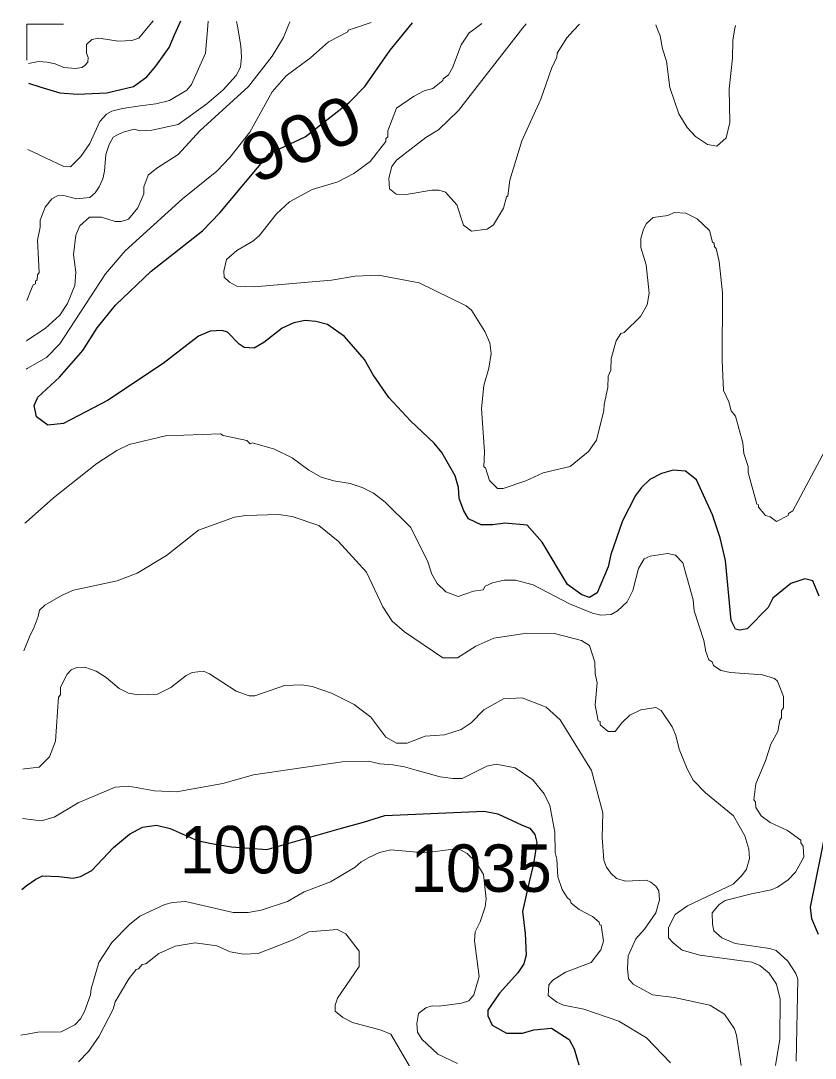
# Model space of a CAD drawing. Extents: x 598.3 to 623.2, y 6902.2 to 6930.1.
# Drawn here: x 598.538 to 599.877, y 6928.329 to 6930.078 of the extents above; entities that cross this region are included whole.
import ezdxf
from ezdxf.enums import TextEntityAlignment as Align

# ---------------------------------------------------------------- set-up
doc = ezdxf.new("R2010")
doc.units = 0
doc.header["$LTSCALE"] = 0.032
for name, color, linetype, lineweight in [('1', 7, 'Continuous', 25), ('2', 7, 'Continuous', 13), ('63', 7, 'Continuous', 13)]:
    doc.layers.add(name, color=color, linetype=linetype, lineweight=lineweight)
doc.layers.add('21', color=7, linetype='Continuous')
doc.layers.add('61', color=7, linetype='Continuous')

msp = doc.modelspace()

# ---------------------------------------------------------------- linework, layer by layer
at = {"layer": '1'}
for points in [[(598.5508, 6929.973), (598.5702, 6929.9669), (598.6037, 6929.9564), (598.6336, 6929.9544), (598.6832, 6929.9565), (598.7279, 6929.9674), (598.7506, 6929.9834), (598.7655, 6930.0018), (598.7878, 6930.0332), (598.7972, 6930.0545), (598.8074, 6930.0777)], [(599.8837, 6929.1081), (599.873, 6929.1342), (599.8597, 6929.1374), (599.8361, 6929.1298), (599.8058, 6929.1048), (599.7978, 6929.089), (599.7622, 6929.0534), (599.7495, 6929.051), (599.7426, 6929.0528), (599.7353, 6929.0671), (599.7257, 6929.1683), (599.7169, 6929.2068), (599.7042, 6929.2453), (599.6772, 6929.3043), (599.6586, 6929.3188), (599.6375, 6929.3205), (599.6181, 6929.3148), (599.5985, 6929.3049), (599.584, 6929.2911), (599.5741, 6929.2779), (599.552, 6929.235), (599.5324, 6929.1783), (599.528, 6929.1579), (599.5095, 6929.1141), (599.4966, 6929.1061), (599.4835, 6929.1102), (599.4593, 6929.1281), (599.4166, 6929.1995), (599.3916, 6929.228), (599.354, 6929.2314), (599.3335, 6929.2283), (599.3138, 6929.2283), (599.2928, 6929.2386), (599.2847, 6929.2522), (599.2768, 6929.2728), (599.2756, 6929.2913), (599.2699, 6929.311), (599.2478, 6929.3502), (599.2349, 6929.3661), (599.1947, 6929.4038), (599.1581, 6929.4429), (599.1318, 6929.4813), (599.1174, 6929.5072), (599.0835, 6929.5458), (599.0551, 6929.5663), (599.0353, 6929.5714), (599.0175, 6929.573), (598.998, 6929.569), (598.9787, 6929.5601), (598.9476, 6929.5357), (598.9313, 6929.5262), (598.9146, 6929.5275), (598.906, 6929.5332), (598.8862, 6929.5531), (598.8774, 6929.556), (598.857, 6929.5551), (598.8372, 6929.5467), (598.7781, 6929.5002), (598.6842, 6929.438), (598.6098, 6929.3992), (598.5835, 6929.3966), (598.5642, 6929.4104), (598.5602, 6929.4297), (598.5668, 6929.4436), (598.6032, 6929.4771), (598.6422, 6929.5222), (598.6667, 6929.5607), (598.6975, 6929.5987), (598.7574, 6929.6562), (598.844, 6929.7242), (598.8732, 6929.7541), (598.9571, 6929.8541), (599.0175, 6929.8825), (599.0919, 6929.9407), (599.118, 6929.9675), (599.1604, 6930.0286), (599.1983, 6930.0745)], [(598.5398, 6928.6138), (598.5469, 6928.6197), (598.5631, 6928.6313), (598.5745, 6928.6366), (598.6018, 6928.6356), (598.6261, 6928.6329), (598.6384, 6928.6355), (598.6578, 6928.6459), (598.6942, 6928.6848), (598.7211, 6928.7068), (598.743, 6928.7191), (598.7665, 6928.7222), (598.7895, 6928.7165), (598.8354, 6928.6966), (598.8591, 6928.6915), (598.893, 6928.6859), (598.9526, 6928.681), (599.0783, 6928.7169), (599.1158, 6928.7274), (599.1517, 6928.7388), (599.3189, 6928.7457), (599.3421, 6928.7415), (599.383, 6928.7224), (599.3959, 6928.7171), (599.4042, 6928.7065), (599.408, 6928.6928), (599.4024, 6928.6572), (599.3948, 6928.627), (599.3837, 6928.5767), (599.3883, 6928.5395), (599.3898, 6928.503), (599.386, 6928.4886), (599.376, 6928.4731), (599.3449, 6928.4391), (599.3254, 6928.4104), (599.3251, 6928.4009), (599.3326, 6928.3854), (599.3569, 6928.3718), (599.3836, 6928.3718), (599.4028, 6928.3774), (599.4324, 6928.3798), (599.4622, 6928.3607), (599.4706, 6928.3453), (599.4788, 6928.318)], [(599.8827, 6928.538), (599.8716, 6928.5641), (599.8691, 6928.584), (599.8966, 6928.7201)]]:
    msp.add_lwpolyline(points, dxfattribs=at)
at = {"layer": '2'}
for points in [[(598.5473, 6929.5383), (598.5482, 6929.5389), (598.5792, 6929.5596), (598.6038, 6929.582), (598.6165, 6929.6016), (598.629, 6929.6319), (598.6305, 6929.6546), (598.6266, 6929.6843), (598.6305, 6929.7169), (598.6374, 6929.7322), (598.6535, 6929.747), (598.6737, 6929.7471), (598.6967, 6929.7398), (598.7069, 6929.7398), (598.7193, 6929.7438), (598.7351, 6929.7627), (598.7454, 6929.7865), (598.7455, 6929.7984), (598.7524, 6929.818), (598.767, 6929.8299), (598.8031, 6929.8524), (598.8399, 6929.8925), (598.9217, 6929.967), (598.9616, 6930.0183), (598.9805, 6930.0496), (598.9884, 6930.0693), (598.9912, 6930.0762)], [(598.9016, 6930.0769), (598.903, 6930.0691), (598.9089, 6930.0361), (598.91, 6930.0168), (598.9085, 6930.0001), (598.9012, 6929.9859), (598.8791, 6929.9617), (598.8515, 6929.9382), (598.8032, 6929.9035), (598.7585, 6929.8935), (598.7388, 6929.8928), (598.7291, 6929.8951), (598.7102, 6929.8904), (598.7, 6929.8853), (598.6937, 6929.8817), (598.6868, 6929.8695), (598.6815, 6929.8529), (598.6792, 6929.8248), (598.6762, 6929.8118), (598.6701, 6929.7982), (598.6633, 6929.7883), (598.6542, 6929.78), (598.6319, 6929.7779), (598.6106, 6929.7836), (598.5995, 6929.783), (598.5904, 6929.7777), (598.5789, 6929.7637), (598.5707, 6929.7417), (598.5706, 6929.7301), (598.5658, 6929.708), (598.569, 6929.6535), (598.5658, 6929.6496), (598.5657, 6929.6414), (598.5626, 6929.6391), (598.5625, 6929.6348), (598.5589, 6929.6331), (598.5545, 6929.6225), (598.5478, 6929.6065)], [(598.5499, 6929.8611), (598.5797, 6929.8469), (598.6106, 6929.8322), (598.6214, 6929.8321), (598.6392, 6929.8493), (598.6542, 6929.8711), (598.6709, 6929.9083), (598.6823, 6929.9204), (598.6915, 6929.9259), (598.7096, 6929.9303), (598.739, 6929.9348), (598.7658, 6929.9379), (598.7884, 6929.9435), (598.8177, 6929.9609), (598.8259, 6929.9709), (598.8494, 6930.0235), (598.8524, 6930.0629), (598.8535, 6930.0773)], [(598.5511, 6930.0063), (598.5676, 6930.0092), (598.5825, 6930.0085), (598.5957, 6930.0054), (598.6104, 6929.9995), (598.6299, 6929.9978), (598.641, 6929.9994), (598.6455, 6930.0019), (598.6511, 6930.0085), (598.6514, 6930.0163), (598.6484, 6930.0237), (598.6484, 6930.0382), (598.6575, 6930.0465), (598.6697, 6930.049), (598.7028, 6930.0437), (598.7251, 6930.0448), (598.7367, 6930.0489), (598.7419, 6930.0551), (598.7612, 6930.0781)], [(599.1287, 6930.0751), (599.1005, 6930.0656), (599.0898, 6930.062), (599.0891, 6930.0593), (599.0568, 6930.0428), (599.0262, 6930.0156), (598.9853, 6929.9852), (598.9615, 6929.9581), (598.9242, 6929.8901), (598.8902, 6929.8474), (598.8683, 6929.8246), (598.8107, 6929.7782), (598.7139, 6929.6904), (598.6806, 6929.6513), (598.6038, 6929.5333), (598.581, 6929.5103), (598.5489, 6929.4922), (598.5469, 6929.4911)], [(599.3152, 6930.0736), (599.2996, 6930.0618), (599.2939, 6930.0575), (599.2804, 6930.0375), (599.2658, 6929.9986), (599.2588, 6929.987), (599.25, 6929.9803), (599.2495, 6929.9774), (599.2327, 6929.9641), (599.2177, 6929.9597), (599.1997, 6929.9507), (599.1711, 6929.9305), (599.1568, 6929.8926), (599.1566, 6929.8826), (599.1535, 6929.8796), (599.1534, 6929.8745), (599.1269, 6929.8411), (599.0992, 6929.8207), (599.0724, 6929.8068), (599.0289, 6929.7934), (598.9908, 6929.773), (598.9691, 6929.7529), (598.9399, 6929.7157), (598.929, 6929.7065), (598.902, 6929.6908), (598.8847, 6929.6755), (598.8799, 6929.6559), (598.8807, 6929.646), (598.8896, 6929.6374), (598.9023, 6929.6306), (598.9311, 6929.6296), (599.0619, 6929.6409), (599.1014, 6929.6475), (599.1411, 6929.649), (599.2092, 6929.6365), (599.2886, 6929.5975), (599.2977, 6929.5905), (599.3204, 6929.5542), (599.3283, 6929.5355), (599.3307, 6929.5174), (599.3268, 6929.4924), (599.3187, 6929.4635), (599.3146, 6929.4247), (599.3194, 6929.3515), (599.3186, 6929.3264), (599.3212, 6929.3247), (599.3282, 6929.303), (599.3414, 6929.2898), (599.3513, 6929.2898), (599.3893, 6929.3024), (599.4183, 6929.316), (599.4638, 6929.3268), (599.4949, 6929.3519), (599.5082, 6929.3713), (599.5209, 6929.4209), (599.5211, 6929.4312), (599.5274, 6929.4597), (599.5282, 6929.4788), (599.5323, 6929.4892), (599.5332, 6929.5089), (599.5418, 6929.5385), (599.5493, 6929.551), (599.5548, 6929.5529), (599.5825, 6929.5796), (599.5939, 6929.5992), (599.597, 6929.619), (599.5922, 6929.6669), (599.5834, 6929.6959), (599.5834, 6929.7111), (599.5875, 6929.727), (599.5928, 6929.7362), (599.6041, 6929.7463), (599.6284, 6929.7501), (599.6395, 6929.7551), (599.659, 6929.7536), (599.6782, 6929.7445), (599.6987, 6929.7247), (599.7041, 6929.705), (599.7069, 6929.7034), (599.7072, 6929.6973), (599.7103, 6929.6945), (599.7152, 6929.6721), (599.721, 6929.6194), (599.7201, 6929.5057), (599.7226, 6929.4546), (599.7313, 6929.4357), (599.7353, 6929.4205), (599.7427, 6929.4117), (599.7548, 6929.3664), (599.7567, 6929.3486), (599.7638, 6929.3269), (599.764, 6929.3167), (599.7784, 6929.2633), (599.7816, 6929.262), (599.7817, 6929.2584), (599.7933, 6929.2444), (599.8014, 6929.2417), (599.8116, 6929.234), (599.8313, 6929.244), (599.832, 6929.2476)], [(599.4797, 6930.0722), (599.4697, 6930.0615), (599.4584, 6930.0494), (599.4418, 6930.0233), (599.4415, 6930.0166), (599.4327, 6929.9978), (599.4148, 6929.946), (599.3825, 6929.8756), (599.3624, 6929.8094), (599.359, 6929.783), (599.3565, 6929.7815), (599.3516, 6929.7622), (599.335, 6929.7343), (599.3242, 6929.7269), (599.2974, 6929.7236), (599.2842, 6929.7333), (599.2729, 6929.7679), (599.2541, 6929.7892), (599.2425, 6929.7924), (599.2306, 6929.7924), (599.1875, 6929.7853), (599.1706, 6929.7859), (599.1597, 6929.7949), (599.1584, 6929.8129), (599.1633, 6929.8323), (599.1712, 6929.8433), (599.2206, 6929.8814), (599.2418, 6929.8942), (599.2756, 6929.9268), (599.3842, 6930.0661), (599.3896, 6930.073)], [(599.6083, 6930.0712), (599.6108, 6930.0651), (599.6158, 6930.0529), (599.6195, 6930.0306), (599.6262, 6930.0101), (599.6321, 6929.9654), (599.6471, 6929.9214), (599.6614, 6929.898), (599.675, 6929.8829), (599.6953, 6929.8693), (599.7111, 6929.8669), (599.7272, 6929.8805), (599.733, 6929.9066), (599.7322, 6929.9632), (599.7379, 6930.0148), (599.738, 6930.0447), (599.7412, 6930.0629), (599.7425, 6930.0701)], [(599.832, 6929.2476), (599.8395, 6929.2522), (599.9069, 6929.3782), (599.9183, 6929.4492), (599.9218, 6929.4577), (599.9257, 6929.4948), (599.9274, 6929.5591), (599.9233, 6929.6142), (599.9241, 6929.6345), (599.9325, 6929.6577), (599.9627, 6929.691), (599.9824, 6929.717), (599.9912, 6929.7349), (599.9969, 6929.7544), (599.9969, 6929.7754), (599.9872, 6929.833), (599.9937, 6929.913), (599.984, 6929.9468), (599.9734, 6930.0037), (599.976, 6930.0596), (599.9764, 6930.0681)], [(598.5448, 6929.2312), (598.5468, 6929.233), (598.5929, 6929.2739), (598.6662, 6929.332), (598.6997, 6929.354), (598.7207, 6929.3639), (598.7821, 6929.3787), (598.8747, 6929.3819), (598.8791, 6929.3789), (598.9187, 6929.3706), (598.9246, 6929.3651), (598.9287, 6929.3665), (598.9656, 6929.356), (598.9951, 6929.3414), (599.0237, 6929.3206), (599.0445, 6929.3086), (599.0654, 6929.3024), (599.0933, 6929.2979), (599.1136, 6929.2911), (599.1324, 6929.2816), (599.1523, 6929.2666), (599.1955, 6929.2241), (599.2243, 6929.166), (599.2306, 6929.1451), (599.2398, 6929.1298), (599.2542, 6929.1154), (599.2753, 6929.1077), (599.3011, 6929.1165), (599.3176, 6929.1191), (599.3209, 6929.1252), (599.3331, 6929.1309), (599.3529, 6929.1352), (599.3718, 6929.1352), (599.4018, 6929.1276), (599.463, 6929.0953), (599.5015, 6929.0793), (599.5155, 6929.0764), (599.5333, 6929.0772), (599.5439, 6929.0836), (599.5598, 6929.0987), (599.5699, 6929.1175), (599.5791, 6929.1551), (599.5885, 6929.1709), (599.5987, 6929.1755), (599.6278, 6929.1804), (599.6417, 6929.1773), (599.6537, 6929.1642), (599.6715, 6929.1019), (599.6729, 6929.0835), (599.6895, 6929.0334), (599.6925, 6929.0148), (599.6979, 6929.001), (599.7032, 6928.9973), (599.7056, 6928.9911), (599.7179, 6928.983), (599.734, 6928.9795), (599.7881, 6928.9756), (599.8086, 6928.9692), (599.8137, 6928.9651), (599.8237, 6928.939), (599.8237, 6928.9202), (599.8205, 6928.9157), (599.8204, 6928.9031), (599.8173, 6928.8993), (599.8139, 6928.8799), (599.8024, 6928.8586), (599.7933, 6928.8309), (599.7769, 6928.7917), (599.7736, 6928.7652), (599.7767, 6928.7616), (599.7769, 6928.7521), (599.7862, 6928.7379), (599.8014, 6928.7269), (599.8305, 6928.7132), (599.8527, 6928.697), (599.8529, 6928.6926), (599.8569, 6928.6869), (599.8577, 6928.6681), (599.8437, 6928.6428), (599.8313, 6928.6303), (599.8133, 6928.6175), (599.8027, 6928.613), (599.7694, 6928.6063), (599.7255, 6928.5953), (599.7152, 6928.5886), (599.7036, 6928.5747), (599.704, 6928.5556), (599.7064, 6928.544), (599.7194, 6928.5321), (599.7422, 6928.5226), (599.8008, 6928.5143), (599.811, 6928.5108), (599.8311, 6928.493), (599.8446, 6928.4724), (599.8479, 6928.4627), (599.8448, 6928.3243)], [(598.543, 6929.0163), (598.5525, 6929.0398), (598.5604, 6929.056), (598.5669, 6929.0739), (598.5692, 6929.0846), (598.5783, 6929.0929), (598.6077, 6929.1099), (598.6266, 6929.1181), (598.7004, 6929.1343), (598.7339, 6929.1471), (598.7834, 6929.1765), (598.8377, 6929.2192), (598.898, 6929.2412), (598.9171, 6929.2443), (598.9724, 6929.246), (598.9954, 6929.2426), (599.0401, 6929.2273), (599.073, 6929.201), (599.1204, 6929.1487), (599.148, 6929.0901), (599.1641, 6929.0662), (599.1848, 6929.0479), (599.2493, 6929.004), (599.2742, 6929.0045), (599.3052, 6929.024), (599.3351, 6929.0372), (599.3912, 6929.046), (599.4374, 6929.0451), (599.4831, 6929.0333), (599.4967, 6929.0249), (599.5056, 6928.997), (599.5064, 6928.9773), (599.5097, 6928.9622), (599.5064, 6928.9247), (599.5113, 6928.8982), (599.5143, 6928.897), (599.5147, 6928.8914), (599.5278, 6928.8803), (599.5401, 6928.8802), (599.5511, 6928.8949), (599.5647, 6928.9076), (599.5831, 6928.9168), (599.6083, 6928.9206), (599.6173, 6928.9157), (599.636, 6928.888), (599.6423, 6928.8736), (599.6475, 6928.8504), (599.661, 6928.817), (599.6716, 6928.7981), (599.6923, 6928.7766), (599.7391, 6928.7381), (599.7587, 6928.7042), (599.7653, 6928.6816), (599.7664, 6928.6663), (599.7611, 6928.648), (599.7533, 6928.6372), (599.7386, 6928.6228), (599.6616, 6928.5861), (599.6408, 6928.5717), (599.6296, 6928.55), (599.6295, 6928.5324), (599.6377, 6928.5237), (599.6527, 6928.5118), (599.6823, 6928.5029), (599.7703, 6928.4915), (599.7838, 6928.4859), (599.7996, 6928.4727), (599.8117, 6928.4545), (599.818, 6928.4287), (599.8172, 6928.3614), (599.81, 6928.317)], [(599.2804, 6928.8837), (599.252, 6928.8744), (599.2196, 6928.872), (599.1894, 6928.8607), (599.1713, 6928.8607), (599.153, 6928.8707), (599.1279, 6928.9041), (599.0998, 6928.9256), (599.0618, 6928.9446), (599.0291, 6928.9562), (599.0116, 6928.9586), (598.9824, 6928.9579), (598.9325, 6928.9402), (598.9231, 6928.9401), (598.9012, 6928.9479), (598.8561, 6928.9775), (598.8458, 6928.982), (598.8269, 6928.9797), (598.8164, 6928.9743), (598.7906, 6928.9544), (598.7684, 6928.9433), (598.7356, 6928.9417), (598.7196, 6928.9449), (598.7036, 6928.9528), (598.6819, 6928.9711), (598.6648, 6928.982), (598.6457, 6928.9885), (598.6324, 6928.9878), (598.6226, 6928.9838), (598.6158, 6928.977), (598.6048, 6928.955), (598.6046, 6928.9417), (598.6014, 6928.9381), (598.5965, 6928.864), (598.5865, 6928.8376), (598.5687, 6928.8202), (598.544, 6928.8171), (598.5414, 6928.8168)], [(599.7524, 6928.317), (599.7444, 6928.368), (599.7408, 6928.3788), (599.7243, 6928.4039), (599.6993, 6928.4186), (599.6391, 6928.4316), (599.6028, 6928.4363), (599.5701, 6928.454), (599.5626, 6928.4635), (599.5607, 6928.4809), (599.5618, 6928.5022), (599.5745, 6928.5304), (599.5891, 6928.5468), (599.6083, 6928.5744), (599.6148, 6928.5964), (599.6132, 6928.6113), (599.6082, 6928.6196), (599.6001, 6928.626), (599.5925, 6928.6298), (599.5575, 6928.6276), (599.5421, 6928.6323), (599.5325, 6928.6412), (599.5254, 6928.6515), (599.521, 6928.6635), (599.5178, 6928.7015), (599.5192, 6928.7428), (599.4999, 6928.8145), (599.4469, 6928.9), (599.4238, 6928.9213), (599.3833, 6928.9367), (599.3514, 6928.9351), (599.3186, 6928.9165), (599.2971, 6928.8948), (599.2804, 6928.8837)], [(598.5407, 6928.7336), (598.5724, 6928.7296), (598.5939, 6928.7357), (598.6344, 6928.7597), (598.6969, 6928.7862), (598.7199, 6928.7878), (598.7632, 6928.7799), (598.8006, 6928.7783), (598.8785, 6928.7927), (598.9303, 6928.8073), (599.0795, 6928.8291), (599.1243, 6928.8299), (599.1431, 6928.8257), (599.1651, 6928.8242), (599.1848, 6928.8204), (599.2042, 6928.8152), (599.2451, 6928.8038), (599.2661, 6928.8007), (599.282, 6928.801), (599.3237, 6928.8219), (599.3391, 6928.8249), (599.3711, 6928.8189), (599.401, 6928.7985), (599.4203, 6928.7752), (599.4295, 6928.7552), (599.4383, 6928.7107), (599.4385, 6928.6762), (599.4416, 6928.6651), (599.4433, 6928.6354), (599.4503, 6928.6136), (599.4587, 6928.6002), (599.464, 6928.5961), (599.4656, 6928.5909), (599.4794, 6928.5803), (599.5015, 6928.5684), (599.5127, 6928.5586), (599.5138, 6928.5541), (599.5161, 6928.5536), (599.5201, 6928.5266), (599.5157, 6928.5119), (599.4996, 6928.4907), (599.4562, 6928.4745), (599.4348, 6928.4611), (599.4278, 6928.4529), (599.4271, 6928.4352), (599.4414, 6928.4237), (599.4525, 6928.4189), (599.487, 6928.4122), (599.5459, 6928.3916), (599.5927, 6928.364), (599.6332, 6928.3219)], [(599.2741, 6928.3204), (599.2409, 6928.3363), (599.2137, 6928.3616), (599.2068, 6928.3736), (599.2053, 6928.3882), (599.2085, 6928.4047), (599.2207, 6928.4146), (599.2312, 6928.4179), (599.2432, 6928.4171), (599.2808, 6928.4222), (599.2929, 6928.4261), (599.3016, 6928.436), (599.3106, 6928.4669), (599.3026, 6928.527), (599.304, 6928.5425), (599.3124, 6928.5592), (599.3208, 6928.5847), (599.3224, 6928.5979), (599.3179, 6928.6393), (599.3048, 6928.6602), (599.2901, 6928.6745), (599.2805, 6928.6799), (599.2719, 6928.6824), (599.2185, 6928.6754), (599.1616, 6928.6809), (599.1423, 6928.6762), (599.1244, 6928.668), (599.1118, 6928.6603), (599.1015, 6928.6512), (599.0601, 6928.627), (599.0158, 6928.6097), (598.9873, 6928.5938), (598.9433, 6928.579), (598.9209, 6928.575), (598.896, 6928.5751), (598.8157, 6928.5935), (598.7935, 6928.5921), (598.7805, 6928.5884), (598.7385, 6928.5688), (598.7209, 6928.555), (598.6911, 6928.5245), (598.6696, 6928.4905), (598.6565, 6928.4465), (598.6556, 6928.4365), (598.6455, 6928.4084), (598.6384, 6928.3958), (598.6291, 6928.3857), (598.606, 6928.3741), (598.5668, 6928.3733), (598.5489, 6928.3702), (598.5378, 6928.3683)], [(598.635, 6928.3236), (598.6522, 6928.3408), (598.67, 6928.3667), (598.6936, 6928.4122), (598.6972, 6928.4242), (598.7198, 6928.4634), (598.7324, 6928.4792), (598.7363, 6928.4799), (598.7423, 6928.4874), (598.7488, 6928.4886), (598.7705, 6928.506), (598.7983, 6928.5181), (598.8318, 6928.5239), (598.8685, 6928.519), (598.8906, 6928.5088), (598.9132, 6928.5046), (598.9381, 6928.5061), (598.997, 6928.529), (599.0235, 6928.5425), (599.0711, 6928.5465), (599.0857, 6928.5389), (599.1081, 6928.51), (599.1081, 6928.4839), (599.072, 6928.4306), (599.0677, 6928.4187), (599.068, 6928.4088), (599.0807, 6928.398), (599.0968, 6928.3896), (599.1452, 6928.3767), (599.1614, 6928.37), (599.1951, 6928.313)]]:
    msp.add_lwpolyline(points, dxfattribs=at)
at = {"layer": '63'}
msp.add_lwpolyline([(598.6099, 6930.0725), (598.5483, 6930.0725), (598.5483, 6930.0118)], dxfattribs=at)

# ---------------------------------------------------------------- texts
at = {"layer": '21'}
msp.add_text('1035', height=0.08, dxfattribs=at).set_placement((599.1951, 6928.6098))
at = {"layer": '61', "width": 1.15}
msp.add_text('900', height=0.08, rotation=23.499, dxfattribs=at).set_placement((599.0262, 6929.8426), align=Align.CENTER)
at = {"layer": '61', "width": 0.95}
msp.add_text('1000', height=0.08, dxfattribs=at).set_placement((598.9194, 6928.641), align=Align.CENTER)

doc.saveas('drawing.dxf')
